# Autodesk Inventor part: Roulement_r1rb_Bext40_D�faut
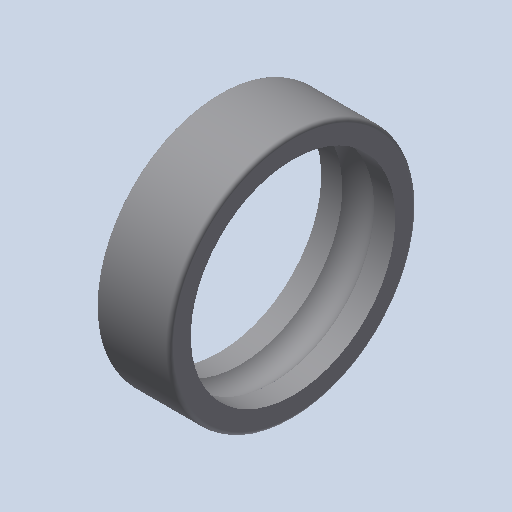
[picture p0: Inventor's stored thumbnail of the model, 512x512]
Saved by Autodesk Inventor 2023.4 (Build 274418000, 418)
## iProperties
Created: 2011-01
Part Number: Roulement_r1rb_Bext40_D�faut
Document SubType Name: Modeling
Designer: eric
Density: 1 g/cm^3
Mass: 4.29648 g
Surface Area: 35.7935 cm^2
Volume: 4.29648 cm^3
Material: Générique
Appearance: Par défaut
Author: eric
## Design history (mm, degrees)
feature "Base1"
node "Corps solides"
node "Corps surfaciques"
node "Solide1"
